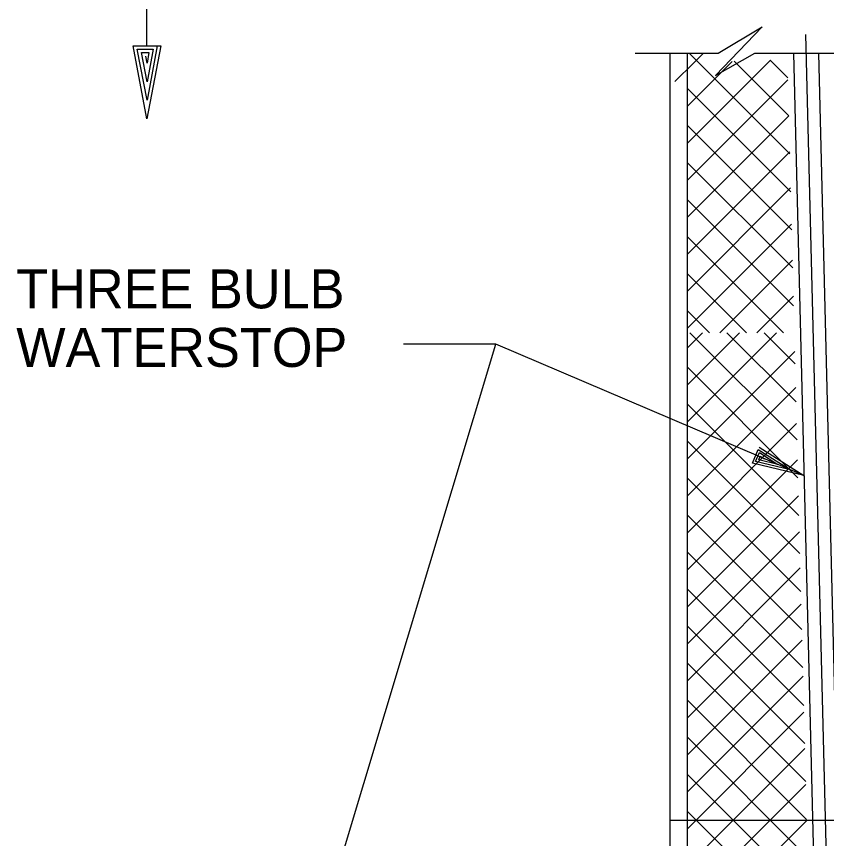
# Model space of a CAD drawing. Extents: x 44743.44 to 44747.1, y 44738.46 to 44741.29.
# Drawn here: x 44744.1132 to 44744.355, y 44740.473 to 44740.7184 of the extents above; entities that cross this region are included whole.
import ezdxf

# ---------------------------------------------------------------- set-up
doc = ezdxf.new("R2010")
doc.units = 0
for name, color, linetype in [('Level 1', 7, 'Continuous'), ('Level 10', 7, 'Continuous'), ('Level 2', 7, 'Continuous'), ('Level 3', 7, 'Continuous'), ('Level 8', 7, 'Continuous'), ('S-ANNO-TEXT', 7, 'Continuous')]:
    doc.layers.add(name, color=color, linetype=linetype)

msp = doc.modelspace()

# ---------------------------------------------------------------- linework, layer by layer
at = {"layer": 'Level 1'}
for p, q in [((44744.33571, 44740.71525), (44744.32177, 44740.70072)), ((44744.32265, 44740.70744), (44744.33571, 44740.71525)), ((44744.34866, 44740.71304), (44744.35779, 44740.34823)), ((44744.29787, 44740.70744), (44744.32265, 44740.70744)), ((44744.32177, 44740.70072), (44744.33358, 44740.70744)), ((44744.33358, 44740.70744), (44744.40232, 44740.70744)), ((44744.30972, 44740.69894), (44744.31537, 44740.70459)), ((44744.34421, 44740.58303), (44744.34421, 44740.58303)), ((44744.3482, 44740.58133), (44744.3482, 44740.58133))]:
    msp.add_line(p, q, dxfattribs=at)
at = {"layer": 'Level 10'}
msp.add_line((44744.30818, 44740.70744), (44744.30818, 44740.45764), dxfattribs=at)
at = {"layer": 'Level 2'}
for p, q in [((44744.31335, 44740.70744), (44744.31335, 44740.45247)), ((44744.34506, 44740.70744), (44744.35393, 44740.35206)), ((44744.35255, 44740.70744), (44744.36143, 44740.35206)), ((44744.1756, 44740.35219), (44744.25626, 44740.62052)), ((44744.30818, 44740.47847), (44744.40086, 44740.47847))]:
    msp.add_line(p, q, dxfattribs=at)
for points in [[(44744.3482, 44740.58133), (44744.25626, 44740.62052), (44744.22875, 44740.62052)], [(44744.33488, 44740.58982), (44744.3482, 44740.58133), (44744.33286, 44740.58506), (44744.33459, 44740.58912), (44744.34421, 44740.58303), (44744.3338, 44740.58557), (44744.3349, 44740.58817), (44744.34038, 44740.58466), (44744.33473, 44740.58607), (44744.33519, 44740.58714), (44744.3364, 44740.58636)]]:
    msp.add_lwpolyline(points, dxfattribs=at)
at = {"layer": 'Level 3'}
msp.add_line((44744.1521, 44740.70967), (44744.1521, 44740.72426), dxfattribs=at)
msp.add_lwpolyline([(44744.15516, 44740.70967), (44744.15625, 44740.70967), (44744.1521, 44740.6878), (44744.14801, 44740.70967), (44744.15516, 44740.70967), (44744.15217, 44740.69338), (44744.14925, 44740.70862), (44744.15396, 44740.70862), (44744.15217, 44740.69888), (44744.15054, 44740.7076), (44744.15272, 44740.7076), (44744.15217, 44740.70446), (44744.15177, 44740.70654)], dxfattribs=at)
at = {"layer": 'Level 8'}
for p, q in [((44744.31335, 44740.70257), (44744.31822, 44740.70744)), ((44744.34398, 44740.67737), (44744.31391, 44740.70744)), ((44744.31335, 44740.68047), (44744.33824, 44740.70537)), ((44744.31335, 44740.69152), (44744.32681, 44740.70497)), ((44744.34369, 44740.68872), (44744.32741, 44740.705)), ((44744.3434, 44740.70006), (44744.33811, 44740.70536)), ((44744.31335, 44740.66943), (44744.34342, 44740.69951)), ((44744.34427, 44740.66603), (44744.31335, 44740.69694)), ((44744.31335, 44740.65838), (44744.34369, 44740.68873)), ((44744.34457, 44740.65468), (44744.31335, 44740.6859)), ((44744.31335, 44740.64735), (44744.34397, 44740.67796)), ((44744.34485, 44740.64334), (44744.31335, 44740.67483)), ((44744.31335, 44740.6363), (44744.34423, 44740.66719)), ((44744.34514, 44740.632), (44744.31335, 44740.66379)), ((44744.31335, 44740.62526), (44744.34451, 44740.65642)), ((44744.34209, 44740.62398), (44744.31335, 44740.65273)), ((44744.32312, 44740.62398), (44744.34479, 44740.64565)), ((44744.33104, 44740.62398), (44744.31335, 44740.64167)), ((44744.33417, 44740.62398), (44744.34507, 44740.63488)), ((44744.31998, 44740.62398), (44744.31335, 44740.63062)), ((44744.31335, 44740.59728), (44744.34005, 44740.62398)), ((44744.31335, 44740.60833), (44744.329, 44740.62398)), ((44744.31335, 44740.61937), (44744.31796, 44740.62398)), ((44744.34614, 44740.59204), (44744.3142, 44740.62398)), ((44744.34586, 44740.60337), (44744.32524, 44740.62398)), ((44744.34557, 44740.6147), (44744.3363, 44740.62398)), ((44744.31335, 44740.58623), (44744.34547, 44740.61837)), ((44744.34643, 44740.5807), (44744.31335, 44740.6138)), ((44744.31335, 44740.57519), (44744.34575, 44740.6076)), ((44744.34672, 44740.56937), (44744.31335, 44740.60275)), ((44744.31335, 44740.56415), (44744.34602, 44740.59683)), ((44744.34701, 44740.55804), (44744.31335, 44740.59169)), ((44744.31335, 44740.55311), (44744.34631, 44740.58606)), ((44744.34731, 44740.54671), (44744.31335, 44740.58066)), ((44744.31335, 44740.54207), (44744.34657, 44740.57529)), ((44744.34759, 44740.53538), (44744.31335, 44740.56962)), ((44744.31335, 44740.53102), (44744.34685, 44740.56452)), ((44744.34788, 44740.52404), (44744.31335, 44740.55856)), ((44744.31335, 44740.51997), (44744.34712, 44740.55375)), ((44744.34816, 44740.51269), (44744.31335, 44740.54751)), ((44744.31335, 44740.50893), (44744.34739, 44740.54297)), ((44744.34845, 44740.50134), (44744.31335, 44740.53644)), ((44744.31335, 44740.49788), (44744.34767, 44740.5322)), ((44744.34873, 44740.49), (44744.31335, 44740.52539)), ((44744.31335, 44740.48685), (44744.34794, 44740.52143)), ((44744.34902, 44740.47866), (44744.31335, 44740.51434)), ((44744.31335, 44740.47581), (44744.34821, 44740.51066)), ((44744.34931, 44740.46732), (44744.31335, 44740.50328)), ((44744.31335, 44740.46476), (44744.34848, 44740.49989)), ((44744.34209, 44740.46348), (44744.31335, 44740.49223)), ((44744.32312, 44740.46348), (44744.34876, 44740.48912)), ((44744.33104, 44740.46348), (44744.31335, 44740.48117)), ((44744.33417, 44740.46348), (44744.34904, 44740.47835))]:
    msp.add_line(p, q, dxfattribs=at)

# ---------------------------------------------------------------- texts
at = {"layer": 'S-ANNO-TEXT'}
for s, p in [('THREE BULB', (44744.11313, 44740.63125)), ('WATERSTOP', (44744.11313, 44740.61375))]:
    msp.add_text(s, height=0.011667, dxfattribs=at).set_placement(p)

doc.saveas('drawing.dxf')
